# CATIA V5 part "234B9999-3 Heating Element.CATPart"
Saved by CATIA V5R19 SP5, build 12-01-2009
Part number: 234B9999-3 Heating Element
Publications: "Over Systems Layup Surface"
Bounding box of the stored display mesh (mm): x 31735.375 to 31922.752, y -11258.356 to -11182.866, z 5357.28 to 5404.578
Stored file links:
  C:\Users\rem1927\Desktop\Current Explicit Composite Demo\234B9999-3 Heating Element.CATPart
  C:\Users\rem1927\Desktop\Current Explicit Composite Demo\234B5678-1 Composite Product.CATProduct
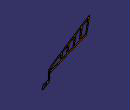
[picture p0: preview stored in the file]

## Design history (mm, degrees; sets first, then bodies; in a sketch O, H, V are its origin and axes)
Set1
  Offset1: Offset DatumSurface4, Length 0
  Extract1: ExtractElem edge [face of Offset1 | face of Offset1]
  Point1: type OnCurve, Support Extract1, Length 12.7
  Plane1: type Normal, Curve Extract1, RefPoint Point1
  Plane2: type Offset, RefPlane Plane1, Offset 5.08
  Plane3: type Offset, RefPlane Plane1, Offset 5.08, reversed
  Intersect1: ToIntersect1 Offset1, ToIntersect2 Plane2
  Intersect2: ToIntersect1 Plane3, ToIntersect2 Offset1
  Extract2: ExtractElem edge [face of Offset1 | face of Offset1]
  Extract3: ExtractElem edge [face of Offset1 | face of Offset1]
  CurvePar1: Offset Extract1, Offset2 0, Offset1 152.4, Support Offset1
  CurvePar2: Offset Extract2, Offset2 0, Offset1 6.35, Support Offset1
  CurvePar3: Offset Extract3, Offset2 0, Offset1 6.35, Support Offset1
  CurvePar4: Offset Extract1, Offset2 0, Offset1 6.35, Support Offset1
  Intersect3: ToIntersect1 Intersect2, ToIntersect2 CurvePar1
  Plane4: type Normal, Curve Intersect2, RefPoint Intersect3
  Plane5: type Offset, RefPlane Plane4, Offset 25.4
  Plane6: type Offset, RefPlane Plane5, Offset 25.4
  Plane7: type Offset, RefPlane Plane6, Offset 25.4
  Plane8: type Offset, RefPlane Plane7, Offset 25.4
  Extract4: ExtractElem face of Offset1
  Intersect4: ToIntersect1 Plane4, ToIntersect2 Extract4
  Intersect5: ToIntersect1 Plane5, ToIntersect2 Extract4
  Intersect6: ToIntersect1 Plane6, ToIntersect2 Extract4
  Intersect7: ToIntersect1 Plane7, ToIntersect2 Extract4
  Intersect8: ToIntersect1 Plane8, ToIntersect2 Extract4
  Split1: ToCut CurvePar2, Cutting (Intersect4; CurvePar4)
  Split2: ToCut CurvePar3, Cutting (Intersect4; CurvePar4)
  CurvePar5: Offset Split1, Offset2 0, Offset1 5.08, Support Extract4
  CurvePar6: Offset Intersect4, Offset2 0, Offset1 5.08, Support Extract4
  CurvePar7: Offset Split2, Offset2 0, Offset1 5.08, Support Extract4
  CurvePar8: Offset Intersect5, Offset2 0, Offset1 5.08, Support Extract4
  CurvePar9: Offset Intersect6, Offset2 0, Offset1 5.08, Support Extract4
  CurvePar10: Offset Intersect8, Offset2 0, Offset1 5.08, Support Extract4
  CurvePar11: Offset CurvePar4, Offset2 0, Offset1 5.08, Support Extract4
  Trim1: Trimmed (CurvePar5; CurvePar6; CurvePar7; Intersect5)
  Trim2: Trimmed (CurvePar5; CurvePar8; CurvePar7; Intersect6)
  Trim3: Trimmed (CurvePar5; CurvePar9; CurvePar7; Intersect7)
  CurvePar12: Offset Intersect7, Offset2 0, Offset1 5.08, Support Extract4
  Trim4: Trimmed (Intersect8; CurvePar5; CurvePar12; CurvePar7)
  Trim5: Trimmed (CurvePar11; CurvePar5; CurvePar10; CurvePar7)
  Trim6: Trimmed (CurvePar4; Split2; Intersect4; Split1)
  Split3: ToCut Extract4, Cutting Trim6
  Split4: ToCut Split3, Cutting (Trim1; Trim2; Trim3; Trim4; Trim5)
  Split5: ToCut Offset1, Cutting (CurvePar4; Intersect1; Intersect2)
  Join1 "Heater Base Surface": Elements (Split5; Split4)
  Set2 "Extract const"
    Extrapol1: ToExtrapol edge of Offset1, Support Join1, Length 6.35
Set3 "const 2"
  Extract5: ExtractElem edge [face of ThickSurface1 | face of ThickSurface1], EXTRACTSOLIDE_SUPPORT face of ThickSurface1
  Plane9: type 1Curve, Element1 Extract5
  CurvePar13: Offset Extract5, Support Plane9, Offset2 0, Offset1 0.508
  Boundary1: Boundary Join1, BoundaryFrom vertex [face of Offset1], BoundaryTo vertex [face of Offset1]
  CurvePar14: Offset Boundary1, Offset2 0, Offset1 0.381, Support Offset1
  Line1: stored without definition
  DatumCurve1
  DatumCurve2
  Line2 to Line4: stored without definition
  DatumCurve3
  Line5 to Line7: stored without definition
  DatumCurve4
  Line8 to Line10: stored without definition
  DatumCurve5
  DatumCurve6
  Line11: stored without definition
  Boundary2: Boundary edge of Split4
  Boundary3: Boundary edge of Split4
  Boundary4: Boundary edge of Split4
  Boundary5: Boundary edge of Split4
  Boundary6: Boundary edge of Split4
  CurvePar15: Offset Boundary6, Offset2 0, Offset1 0.381, Support Offset1
  CurvePar16: Offset Boundary5, Offset2 0, Offset1 0.381, Support Offset1
  CurvePar17: Offset Boundary4, Offset2 0, Offset1 0.381, Support Offset1
  CurvePar18: Offset Boundary3, Offset2 0, Offset1 0.381, Support Offset1
  CurvePar19: Offset Boundary2, Offset2 0, Offset1 0.381, Support Offset1
  DatumCurve7
  Line12: stored without definition
  DatumCurve8
  Line13: stored without definition
  Line14: stored without definition
  DatumCurve9
  Line15: stored without definition
  DatumCurve10
  Line16: stored without definition
  DatumCurve11
  Line17: stored without definition
  DatumCurve12
  Line18: stored without definition
  DatumCurve13
  Line19: stored without definition
  DatumCurve14
  Line20: stored without definition
  DatumCurve15
  Line21: stored without definition
  DatumCurve16
  Boundary7: Boundary face of ThickSurface1
  Line22: stored without definition
  DatumCurve17
  Line23: stored without definition
  Line24: stored without definition
  DatumCurve18
  Line25: stored without definition
  DatumCurve19
  Line26: stored without definition
  DatumCurve20
  Line27: stored without definition
  DatumCurve21
  Line28: stored without definition
  DatumCurve22
  Line29: stored without definition
  DatumCurve23
  Line30: stored without definition
  DatumCurve24
  Line31: stored without definition
  DatumCurve25
  Line32: stored without definition
  DatumCurve26
  Line33: stored without definition
  DatumCurve27
  Line34: stored without definition
  DatumCurve28
  Line35: stored without definition
  DatumCurve29
  Line36: stored without definition
  Extract6: ExtractElem face of ThickSurface1
  Boundary8: Boundary Extract6
  DatumCurve30
  DatumCurve31
  Line37: stored without definition
  Line38: stored without definition
  DatumCurve32
  DatumCurve33
  Line39: type PtPt, FirstPoint vertex of Line37, SecondPoint vertex of Line11
  Line40: type PtPt, FirstPoint vertex of DatumCurve31, SecondPoint vertex of DatumCurve6
  Line41: type PtPt, FirstPoint vertex of DatumCurve30, SecondPoint vertex of DatumCurve5
  Line42: type PtPt, FirstPoint vertex of Line22, SecondPoint vertex of Line10
  Line43: type PtPt, FirstPoint vertex of Line26, SecondPoint vertex of Line9
  Line44: type PtPt, FirstPoint vertex of DatumCurve19, SecondPoint vertex of Line8
  Line45: type PtPt, FirstPoint vertex of Line25, SecondPoint vertex of Line6
  Line46: type PtPt, FirstPoint vertex of DatumCurve18, SecondPoint vertex of Line5
  Line47: type PtPt, FirstPoint vertex of Line24, SecondPoint vertex of Line3
  Line48: type PtPt, FirstPoint vertex of Line23, SecondPoint vertex of Line2
  Line49: type PtPt, FirstPoint vertex of Line23, SecondPoint vertex of DatumCurve2
  Line50: type PtPt, FirstPoint vertex of DatumCurve32, SecondPoint vertex of DatumCurve1
  Line51: type PtPt, FirstPoint vertex of Line38, SecondPoint vertex of Line1
  Line52: type PtPt, FirstPoint vertex of Line38, SecondPoint vertex of Line1
  Line53: type PtPt, FirstPoint vertex of DatumCurve21, SecondPoint vertex of DatumCurve7
  Line54: type PtPt, FirstPoint vertex of Line27, SecondPoint vertex of DatumCurve7
  Line55: type PtPt, FirstPoint vertex of DatumCurve20, SecondPoint vertex of DatumCurve8
  Line56: type PtPt, FirstPoint vertex of DatumCurve20, SecondPoint vertex of Line12
  Line57: type PtPt, FirstPoint vertex of DatumCurve22, SecondPoint vertex of DatumCurve9
  Line58: type PtPt, FirstPoint vertex of Line29, SecondPoint vertex of Line15
  Line59: type PtPt, FirstPoint vertex of DatumCurve23, SecondPoint vertex of Line14
  Line60: type PtPt, FirstPoint vertex of DatumCurve22, SecondPoint vertex of Line14
  Line61: type PtPt, FirstPoint vertex of DatumCurve24, SecondPoint vertex of DatumCurve11
  Line62: type PtPt, FirstPoint vertex of Line31, SecondPoint vertex of Line17
  Line63: type PtPt, FirstPoint vertex of DatumCurve25, SecondPoint vertex of Line16
  Line64: type PtPt, FirstPoint vertex of DatumCurve24, SecondPoint vertex of Line16
  Line65: type PtPt, FirstPoint vertex of DatumCurve26, SecondPoint vertex of DatumCurve13
  Line66: type PtPt, FirstPoint vertex of Line33, SecondPoint vertex of Line19
  Line67: type PtPt, FirstPoint vertex of DatumCurve27, SecondPoint vertex of Line18
  Line68: type PtPt, FirstPoint vertex of DatumCurve26, SecondPoint vertex of Line18
  Line69: type PtPt, FirstPoint vertex of DatumCurve28, SecondPoint vertex of DatumCurve15
  Line70: type PtPt, FirstPoint vertex of Line35, SecondPoint vertex of Line21
  Line71: type PtPt, FirstPoint vertex of DatumCurve29, SecondPoint vertex of Line20
  Line72: type PtPt, FirstPoint vertex of DatumCurve28, SecondPoint vertex of Line20
  Loft1: Sections (Line53; Line56), Guides (Line28; Line12)
  Loft2: Sections (Line53; Line54), Guides (DatumCurve21; DatumCurve7)
  Loft3: Sections (Line54; Line55), Guides (Line27; Line13)
  Loft4: Sections (Line55; Line56), Guides (DatumCurve20; DatumCurve8)
  Loft5: Sections (Line44; Line43), Guides (Line26; Line9)
  Loft6: Sections (Line43; Line42), Guides (Line22; Line10)
  Loft7: Sections (Line42; Line41), Guides (DatumCurve30; DatumCurve5)
  Loft8: Sections (Line41; Line40), Guides (DatumCurve31; DatumCurve6)
  Loft9: Sections (Line40; Line39), Guides (Line37; Line11)
  Loft10: Sections (Line52; Line51), Guides (Line38; Line1)
  Loft11: Sections (Line50; Line51), Guides (DatumCurve32; DatumCurve1)
  Loft12: Sections (Line50; Line49), Guides (DatumCurve33; DatumCurve2)
  Loft13: Sections (Line49; Line48), Guides (Line23; Line2)
  Loft14: Sections (Line47; Line48), Guides (Line24; Line3)
  Join2: Elements (Line8; DatumCurve4; Line7)
  Loft15: Sections (Line45; Line44), Guides (DatumCurve19; Join2)
  Loft16: Sections (Line45; Line46), Guides (Line25; Line6)
  Join3: Elements (Line5; DatumCurve3; Line4)
  Loft17: Sections (Line47; Line46), Guides (DatumCurve18; Join3)
  Loft18: Sections (Line72; Line69), Guides (DatumCurve28; DatumCurve15)
  Loft19: Sections (Line69; Line70), Guides (Line35; Line21)
  Loft20: Sections (Line70; Line71), Guides (DatumCurve29; DatumCurve16)
  Loft21: Sections (Line71; Line72), Guides (Line36; Line20)
  Loft22: Sections (Line68; Line67), Guides (Line34; Line18)
  Loft23: Sections (Line67; Line66), Guides (DatumCurve27; DatumCurve14)
  Loft24: Sections (Line66; Line65), Guides (Line33; Line19)
  Loft25: Sections (Line65; Line68), Guides (DatumCurve26; DatumCurve13)
  Loft26: Sections (Line64; Line63), Guides (Line32; Line16)
  Loft27: Sections (Line63; Line62), Guides (DatumCurve25; DatumCurve12)
  Loft28: Sections (Line61; Line62), Guides (Line31; Line17)
  Loft29: Sections (Line61; Line64), Guides (DatumCurve24; DatumCurve11)
  Loft30: Sections (Line60; Line59), Guides (Line30; Line14)
  Loft31: Sections (Line60; Line57), Guides (DatumCurve22; DatumCurve9)
  Loft32: Sections (Line57; Line58), Guides (Line29; Line15)
  Loft33: Sections (Line58; Line59), Guides (DatumCurve23; DatumCurve10)
  DatumSurface1 to DatumSurface3
  Join4: Elements (Loft9; DatumSurface2; Loft10; Loft11; DatumSurface3; Loft8; Loft7; DatumSurface1; Loft12; Loft6; Extract7; Loft13; Loft14; Loft5; Loft15; Loft4; Loft1; Loft3; Loft2; Loft17; Loft32; Loft31; Loft33; Loft30; Loft28; Loft29; Loft27; Loft26; Loft24; Loft25; Loft23; Loft22; Loft20; Loft19; Loft21; Loft18; Loft16)
  Extract7: ExtractElem face of ThickSurface1
  Boundary9: Boundary edge of Loft10, BoundaryFrom vertex [face of Loft10], BoundaryTo vertex [face of Loft9]
  Boundary10: Boundary edge of Loft3
  Boundary11: Boundary edge of Loft30
  Boundary12: Boundary edge of Loft26
  Boundary13: Boundary edge of Loft22
  Boundary14: Boundary edge of Loft21
  Split6: ToCut Offset1, Cutting Boundary14
  Split7: ToCut Offset1, Cutting Boundary13
  Split8: ToCut Offset1, Cutting Boundary12
  Split9: ToCut Offset1, Cutting Boundary11
  Split10: ToCut Offset1, Cutting Boundary10
  Split11: ToCut Offset1, Cutting Boundary9
  Join5 "Over Systems Layup Surface": Elements (Split11; Split6; Split7; Split8; Split9; Split10; Join4)
Set4
  DatumSurface4 "Lay up top of ID tag": linked copy from another document
Body1 "Heater Solid" (main body)
  ThickSurface1: Surface Extrapol1, TopOffset 0.381, BotOffset 0
  Body2 "Connector"
    Pad1: profile CurvePar13, length 0.254, opposite side length 6.35
  Add1: tool Body2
